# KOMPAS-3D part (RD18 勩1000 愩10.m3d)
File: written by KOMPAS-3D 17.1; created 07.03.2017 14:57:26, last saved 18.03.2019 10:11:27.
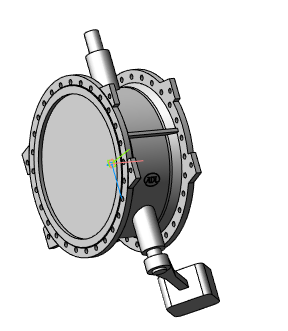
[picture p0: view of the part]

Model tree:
1. Операция без истории:2  (labels: Сталь 20  ГОСТ 1050-88)

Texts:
  RD18 Ду100 Ру16
  RD18 Ду150 Ру16
  RD18 Ду200 Ру16
  RD18 Ду250 Ру16
  RD18 Ду300 Ру16
  RD18 Ду350 Ру16
  RD18 Ду400 Ру10
  RD18 Ду400 Ру16
  RD18 Ду450 Ру10
  RD18 Ду450 Ру16
  RD18 Ду500 Ру10
  RD18 Ду500 Ру16
  RD18 Ду600 Ру10
  RD18 Ду600 Ру16
  RD18 Ду700 Ру10
  RD18 Ду700 Ру16
  RD18 Ду800 Ру10
  RD18 Ду800 Ру16
  RD18 Ду900 Ру10
  RD18 Ду900 Ру16
  RD18 Ду1000 Ру10
  RD18 Ду1000 Ру16
  RD18 Ду1200 Ру16
  RD18 Ду1400 Ру16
